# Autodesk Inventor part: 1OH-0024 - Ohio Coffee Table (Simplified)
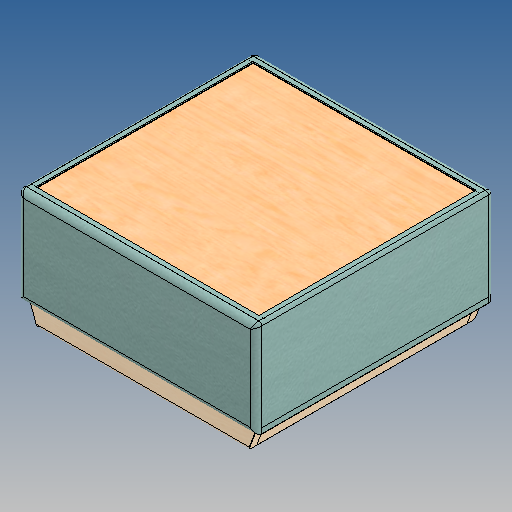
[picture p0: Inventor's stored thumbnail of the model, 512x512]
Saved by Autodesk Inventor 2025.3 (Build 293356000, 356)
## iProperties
Created: 2025-11
Part Number: 1OH-0024 - Ohio Coffee Table (Simplified)
Material: Generic
Document SubType Name: Modeling
Designer: craig.ferris
Density: 1 g/cm^3
Appearance: CADET-ZEST SEAFOAM (219)
Author: craig.ferris
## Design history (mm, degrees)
node "Assembly1"
body "Solid1"
node "Part1:1"
node "Part2:1"
body "Solid2"
node "Part1:2"
body "Solid3"
node "Part2:2"
body "Solid4"
node "Part3:1"
body "Solid5"
node "Part4:1"
body "Solid6"
node "Part5:1"
body "Solid7"
node "Part6:1"
body "Solid8"
node "Part7:1"
body "Solid9"
node "Part8:1"
body "Solid10"
node "Part9:1"
body "Solid11"
node "Part10:1"
body "Solid12"
node "Part11:1"
body "Solid13"
node "Part12:1"
body "Solid14"
node "Part13:1"
body "Solid15"
node "Part14:1"
body "Solid16"
node "Part15:1"
body "Solid17"
